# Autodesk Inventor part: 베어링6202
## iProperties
IsCustomPart: 0
Company: 한국ATC센터
Created: 2014-12
Part Number: 베어링6202
Material: 강, 연강
Description: 깊은 그루브 볼 베어링
Document SubType Name: Modeling
Standard: KS B 2023
Designer: KYOUNG IL JANG
Standards Organization: KS
Language: ko-KR
Size Designation: 6202 - 15 x 35 x 11
Categories: <MemberInstance><Categories><Category DisplayName="샤프트 부품" InternalName="7f7aeb1f-a693-4053-b835-cee3144e0d98" Mnemonic="SHFT"><Category DisplayName="베어링" Inter
Density: 7.86 g/cm^3
Mass: 45.8725 g
Surface Area: 51.5584 cm^2
Volume: 5.83619 cm^3
Author: KYOUNG IL JANG
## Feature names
1. IDS_ARRAYBALL[SIMPL:T] [Circular Pattern]
